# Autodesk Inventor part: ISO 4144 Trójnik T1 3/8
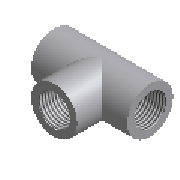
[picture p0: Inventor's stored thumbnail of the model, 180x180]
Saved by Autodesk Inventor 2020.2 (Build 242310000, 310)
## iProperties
Manager: www.cadconsulting.pl
Company: Fabian Stasiak CAD Consulting
NAME: PIPING: ISO 4144 Tee B1
DATA: <meta><inlinegroups number="1" deflen="5.6"></inlinegroups><connections number="3"></connections><angles><a>3.14159265358979</a><a>1.5707963267949</a></angles><
IsCustomPart: 0
Created: 2014-02
Part Number: ISO 4144 Trójnik T1 3/8
Material: Stal nierdzewna
Description: Rurociągi - Elementy ze stali nierdzewnej gwintowane zgodnie z ISO 7-1
Document SubType Name: Modeling
Standard: ISO 4144
Designer: F.Stasiak
Standard Revision: Second edition 2003-03-15
Standards Organization: ISO
Language: pl-PL
Size Designation: 3/8
Categories: <MemberInstance><Categories><Category DisplayName="Rury cienko- i grubościenne" InternalName="4347fa0f-2144-441d-94cd-e3e15c92b736" Mnemonic="TUBEANDPIPE"><Cate
Density: 1 g/cm^3
Appearance: Częściowo polerowana
Catalog Web Link: www.expertbooks.pl
Author: F.Stasiak
Subject: Zbiór ćwiczeń. Autodesk Inventor 2020. Kurs Professional
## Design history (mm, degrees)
sketch "Sketch1"
  geometry: L1 (0, 0)-(50, 0); L2 (50, 0)-(50, 7.475); L3 (25, 0)-(25, 10.75); L4 (0, 0)-(0, 7.475); L5 (0, 7.475)-(9.7, 7.172); L6 (50, 7.475)-(40.3, 7.172); L7 (0, 7.475)-(0, 10.75); L8 (50, 7.475)-(50, 10.75); L9 (9.7, 7.172)-(40.3, 7.172); L10 (0, 10.75)-(50, 10.75); L11 (9.7, 7.172)-(9.7, 0); L12 (40.3, 7.172)-(40.3, 0)
  constraints: 24 end point, 4 perpendicular, 2 midpoint, 2 parallel, 2 point on line, 2 symmetric about line, 1 horizontal, 3 other
  dimensions: "d0" = 14.95 diameter of L4.end L1 (= MD); "d1" = 9.7 horizontal distance of L4.end L5.end (= L); "d2" = 25 distance between parallel lines of L3 L4 (= a); "d3" = 1.78991 deg angle of L1 L5; "d10" = 21.5 diameter of L10 L1 (= d)
revolve "Revolution1" sketch "Sketch1" stored, may be unused: angle "d8" = 90 deg
workplane "Work Plane1"
sketch "Sketch2"
  geometry: L1 (0, 0)-(50, 0) reference; L2 (25, 0)-(25, 10.75) reference; C1 r 10.75 at (25, 0); C2 r 7.475 at (25, 0)
  constraints: 2 centre point, 1 coincident, 1 concentric, 1 point on line
  dimensions: "d5" = 21.5 diameter of C1 (= d); "d7" = 14.95 diameter of C2 (= MD)
extrude "Extrusion1" join sketch "Sketch2" taper "d6" = 0 deg; stored distance "d11" = 10
extrude "Extrusion2" cut sketch "Sketch2" taper "d9" = -1.78991 deg; stored distance "d17" = 4.85 (= 0.5 x L)
workplane "Work Plane2"
sketch "Sketch3"
  geometry: L1 (50, 0)-(0, 0) reference; L2 (25, 0)-(25, 25); L3 (25, 25)-(15.3, 25); L4 (15.3, 25)-(15.3, 15.3); L5 (15.3, 15.3)-(25, 15.3)
  constraints: 8 end point, 4 perpendicular, 1 midpoint, 1 point on line
  dimensions: "d42" = 25 distance of L2.start L2.end (= a); "d43" = 9.7 distance of L2.end L3.end (= L); "d44" = 9.7 distance of L3.end L4.end (= L)
workpoint "Work Point2"
workpoint "Work Point3"
workpoint "Work Point4"
workaxis "Work Axis2"
workpoint "Work Point5"
workaxis "Work Axis3"
workaxis "Work Axis4"
workpoint "Work Point6"
workaxis "Work Axis5"
workpoint "Work Point7"
body "Solid1"
feature "Gwint1" dims "d23" = 10, "d24" = 0
feature "Gwint2" dims "d25" = 10, "d26" = 0
feature "Gwint3" dims "d12" = 9.7 (= L), "d13" = 0
other parameters: "a" = 25 [user parameter; used in 3 equation terms], "d" = 21.5 [user parameter; used in 2 equation terms], "MD" = 14.95 [user parameter; used in 2 equation terms], "L" = 9.7 [user parameter; used in 5 equation terms], "d4" = 25 (= a), "Size_Designation" = 3.75 [user parameter]
